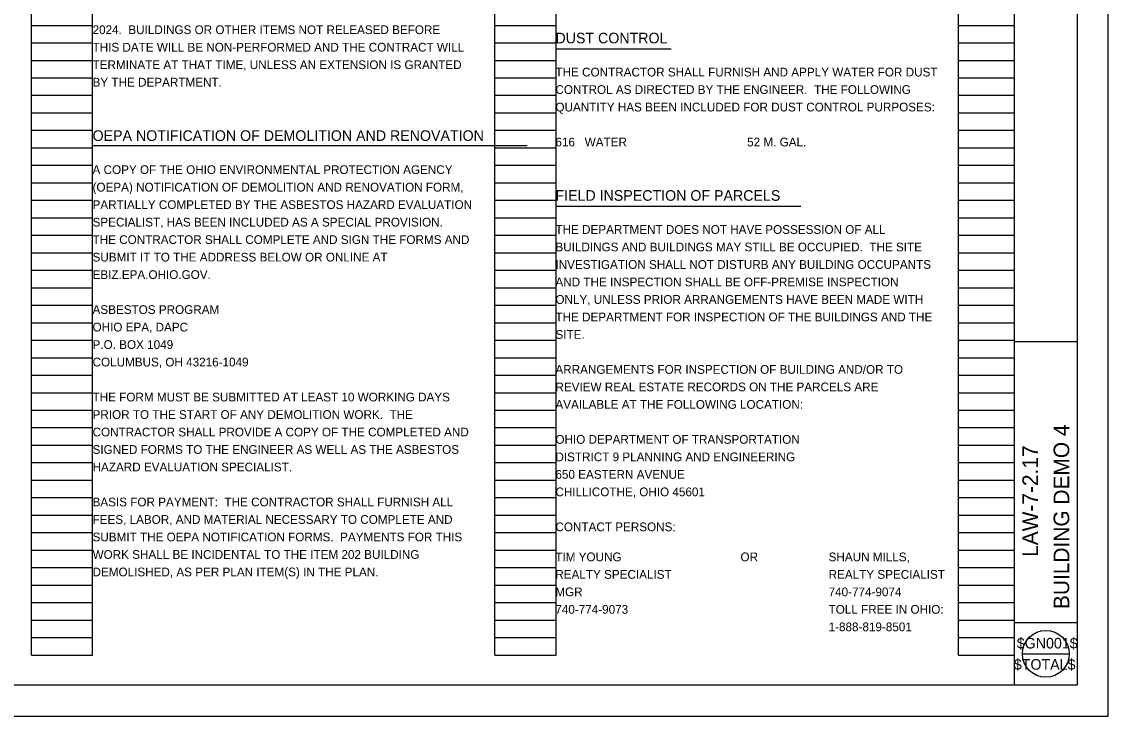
# Model space of a CAD drawing. Extents: x 0 to 34, y 0 to 22.
# Drawn here: x 16.61 to 34, y 0 to 11.12 of the extents above; entities that cross this region are included whole.
import ezdxf

# ---------------------------------------------------------------- set-up
doc = ezdxf.new("R2010")
doc.units = 0
for name, color, linetype in [('Default', 7, 'Continuous'), ('SC_Scratch2', 7, 'Continuous'), ('SH_Border', 7, 'Continuous'), ('SH_Cut_Line', 7, 'Continuous'), ('SH_Data', 7, 'Continuous'), ('TX_P_1', 7, 'Continuous')]:
    doc.layers.add(name, color=color, linetype=linetype)

msp = doc.modelspace()

# ---------------------------------------------------------------- linework, layer by layer
at = {"layer": 'SC_Scratch2'}
for p, q in [((16.76, 0.98), (16.76, 21.14)), ((17.74, 0.98), (17.74, 21.14)), ((24.18, 0.98), (24.18, 21.14)), ((25.16, 0.98), (25.16, 21.14)), ((31.6, 0.98), (31.6, 21.14)), ((32.5, 0.98), (32.5, 21.14)), ((16.76, 11.06), (17.74, 11.06)), ((24.18, 11.06), (25.16, 11.06)), ((31.6, 11.06), (32.5, 11.06)), ((16.76, 10.78), (17.74, 10.78)), ((24.18, 10.78), (25.16, 10.78)), ((31.6, 10.78), (32.5, 10.78)), ((16.76, 10.5), (17.74, 10.5)), ((24.18, 10.5), (25.16, 10.5)), ((31.6, 10.5), (32.5, 10.5)), ((16.76, 10.22), (17.74, 10.22)), ((24.18, 10.22), (25.16, 10.22)), ((31.6, 10.22), (32.5, 10.22)), ((16.76, 9.94), (17.74, 9.94)), ((24.18, 9.94), (25.16, 9.94)), ((31.6, 9.94), (32.5, 9.94)), ((16.76, 9.66), (17.74, 9.66)), ((24.18, 9.66), (25.16, 9.66)), ((31.6, 9.66), (32.5, 9.66)), ((16.76, 9.38), (17.74, 9.38)), ((24.18, 9.38), (25.16, 9.38)), ((31.6, 9.38), (32.5, 9.38)), ((16.76, 9.1), (17.74, 9.1)), ((24.18, 9.1), (25.16, 9.1)), ((31.6, 9.1), (32.5, 9.1)), ((16.76, 8.82), (17.74, 8.82)), ((24.18, 8.82), (25.16, 8.82)), ((31.6, 8.82), (32.5, 8.82)), ((16.76, 8.54), (17.74, 8.54)), ((24.18, 8.54), (25.16, 8.54)), ((31.6, 8.54), (32.5, 8.54)), ((16.76, 8.26), (17.74, 8.26)), ((24.18, 8.26), (25.16, 8.26)), ((31.6, 8.26), (32.5, 8.26)), ((16.76, 7.98), (17.74, 7.98)), ((24.18, 7.98), (25.16, 7.98)), ((31.6, 7.98), (32.5, 7.98)), ((16.76, 7.7), (17.74, 7.7)), ((24.18, 7.7), (25.16, 7.7)), ((31.6, 7.7), (32.5, 7.7)), ((16.76, 7.42), (17.74, 7.42)), ((24.18, 7.42), (25.16, 7.42)), ((31.6, 7.42), (32.5, 7.42)), ((16.76, 7.14), (17.74, 7.14)), ((24.18, 7.14), (25.16, 7.14)), ((31.6, 7.14), (32.5, 7.14)), ((16.76, 6.86), (17.74, 6.86)), ((24.18, 6.86), (25.16, 6.86)), ((31.6, 6.86), (32.5, 6.86)), ((16.76, 6.58), (17.74, 6.58)), ((24.18, 6.58), (25.16, 6.58)), ((31.6, 6.58), (32.5, 6.58)), ((16.76, 6.3), (17.74, 6.3)), ((24.18, 6.3), (25.16, 6.3)), ((31.6, 6.3), (32.5, 6.3)), ((16.76, 6.02), (17.74, 6.02)), ((24.18, 6.02), (25.16, 6.02)), ((31.6, 6.02), (32.5, 6.02)), ((16.76, 5.74), (17.74, 5.74)), ((24.18, 5.74), (25.16, 5.74)), ((31.6, 5.74), (32.5, 5.74)), ((16.76, 5.46), (17.74, 5.46)), ((24.18, 5.46), (25.16, 5.46)), ((31.6, 5.46), (32.5, 5.46)), ((16.76, 5.18), (17.74, 5.18)), ((24.18, 5.18), (25.16, 5.18)), ((31.6, 5.18), (32.5, 5.18)), ((16.76, 4.9), (17.74, 4.9)), ((24.18, 4.9), (25.16, 4.9)), ((31.6, 4.9), (32.5, 4.9)), ((16.76, 4.62), (17.74, 4.62)), ((24.18, 4.62), (25.16, 4.62)), ((31.6, 4.62), (32.5, 4.62)), ((16.76, 4.34), (17.74, 4.34)), ((24.18, 4.34), (25.16, 4.34)), ((31.6, 4.34), (32.5, 4.34)), ((16.76, 4.06), (17.74, 4.06)), ((24.18, 4.06), (25.16, 4.06)), ((31.6, 4.06), (32.5, 4.06)), ((16.76, 3.78), (17.74, 3.78)), ((24.18, 3.78), (25.16, 3.78)), ((31.6, 3.78), (32.5, 3.78)), ((16.76, 3.5), (17.74, 3.5)), ((24.18, 3.5), (25.16, 3.5)), ((31.6, 3.5), (32.5, 3.5)), ((16.76, 3.22), (17.74, 3.22)), ((24.18, 3.22), (25.16, 3.22)), ((31.6, 3.22), (32.5, 3.22)), ((16.76, 2.94), (17.74, 2.94)), ((24.18, 2.94), (25.16, 2.94)), ((31.6, 2.94), (32.5, 2.94)), ((16.76, 2.66), (17.74, 2.66)), ((24.18, 2.66), (25.16, 2.66)), ((31.6, 2.66), (32.5, 2.66)), ((16.76, 2.38), (17.74, 2.38)), ((24.18, 2.38), (25.16, 2.38)), ((31.6, 2.38), (32.5, 2.38)), ((16.76, 2.1), (17.74, 2.1)), ((24.18, 2.1), (25.16, 2.1)), ((31.6, 2.1), (32.5, 2.1)), ((16.76, 1.82), (17.74, 1.82)), ((24.18, 1.82), (25.16, 1.82)), ((31.6, 1.82), (32.5, 1.82)), ((16.76, 1.54), (17.74, 1.54)), ((24.18, 1.54), (25.16, 1.54)), ((31.6, 1.54), (32.5, 1.54)), ((16.76, 1.26), (17.74, 1.26)), ((24.18, 1.26), (25.16, 1.26)), ((31.6, 1.26), (32.5, 1.26)), ((16.76, 0.98), (17.74, 0.98)), ((24.18, 0.98), (25.16, 0.98)), ((31.6, 0.98), (32.5, 0.98))]:
    msp.add_line(p, q, dxfattribs=at)
at = {"layer": 'SH_Border'}
for p, q in [((32.5, 0.5), (32.5, 21.5)), ((32.5, 6), (33.5, 6)), ((32.5, 1.5), (33.5, 1.5))]:
    msp.add_line(p, q, dxfattribs=at)
msp.add_lwpolyline([(2, 21.5), (33.5, 21.5), (33.5, 0.5), (2, 0.5)], close=True, dxfattribs=at)
at = {"layer": 'SH_Cut_Line'}
msp.add_lwpolyline([(0, 0), (34, 0), (34, 22), (0, 22)], close=True, dxfattribs=at)
at = {"layer": 'SH_Data'}
for p, q in [((33, 3.792), (33, 3.792)), ((33, 1.085), (33, 1.085)), ((32.625, 1), (33.375, 1)), ((33, 0.745), (33, 0.745))]:
    msp.add_line(p, q, dxfattribs=at)
msp.add_circle((33, 1), 0.375, dxfattribs=at)
at = {"layer": 'TX_P_1'}
for p, q in [((25.157, 10.685), (27, 10.685)), ((17.747, 9.138), (24.698, 9.138)), ((25.157, 8.165), (29.079, 8.165))]:
    msp.add_line(p, q, dxfattribs=at)

# ---------------------------------------------------------------- texts
at = {"layer": 'Default'}
for s, p in [('TIM YOUNG', (25.148, 2.481)), ('OR', (28.112, 2.481)), ('SHAUN MILLS,', (29.523, 2.481)), ('REALTY SPECIALIST', (25.148, 2.201)), ('REALTY SPECIALIST', (29.523, 2.201)), ('MGR', (25.148, 1.921)), ('740-774-9074', (29.523, 1.921)), ('740-774-9073', (25.148, 1.641)), ('TOLL FREE IN OHIO:', (29.523, 1.641)), ('1-888-819-8501', (29.523, 1.361))]:
    msp.add_text(s, height=0.14, dxfattribs=at).set_placement(p)
at = {"layer": 'SH_Data'}
for s, p in [('BUILDING DEMO 4', (33.375, 1.717)), ('LAW-7-2.17', (32.875, 2.552))]:
    msp.add_text(s, height=0.25, rotation=90, dxfattribs=at).set_placement(p)
for s, p in [('$GN001$', (32.536, 1.085)), ('$TOTAL$', (32.489, 0.745))]:
    msp.add_text(s, height=0.17, dxfattribs=at).set_placement(p)
at = {"layer": 'TX_P_1'}
for s, height, p in [('2024.  BUILDINGS OR OTHER ITEMS NOT RELEASED BEFORE ', 0.14, (17.74, 10.92)), ('DUST CONTROL', 0.17, (25.15, 10.772)), ('THIS DATE WILL BE NON-PERFORMED AND THE CONTRACT WILL ', 0.14, (17.74, 10.64)), ('TERMINATE AT THAT TIME, UNLESS AN EXTENSION IS GRANTED ', 0.14, (17.74, 10.36)), ('THE CONTRACTOR SHALL FURNISH AND APPLY WATER FOR DUST ', 0.14, (25.15, 10.242)), ('BY THE DEPARTMENT.', 0.14, (17.74, 10.08)), ('CONTROL AS DIRECTED BY THE ENGINEER.  THE FOLLOWING ', 0.14, (25.15, 9.962)), ('QUANTITY HAS BEEN INCLUDED FOR DUST CONTROL PURPOSES:', 0.14, (25.15, 9.682)), ('OEPA NOTIFICATION OF DEMOLITION AND RENOVATION', 0.17, (17.74, 9.21)), ('616   WATER                                     52 M. GAL.', 0.14, (25.15, 9.122)), ('A COPY OF THE OHIO ENVIRONMENTAL PROTECTION AGENCY', 0.14, (17.74, 8.68)), ('(OEPA) NOTIFICATION OF DEMOLITION AND RENOVATION FORM, ', 0.14, (17.74, 8.4)), ('FIELD INSPECTION OF PARCELS', 0.17, (25.15, 8.252)), ('PARTIALLY COMPLETED BY THE ASBESTOS HAZARD EVALUATION ', 0.14, (17.74, 8.12)), ('SPECIALIST, HAS BEEN INCLUDED AS A SPECIAL PROVISION.  ', 0.14, (17.74, 7.84)), ('THE DEPARTMENT DOES NOT HAVE POSSESSION OF ALL ', 0.14, (25.15, 7.722)), ('THE CONTRACTOR SHALL COMPLETE AND SIGN THE FORMS AND ', 0.14, (17.74, 7.56)), ('BUILDINGS AND BUILDINGS MAY STILL BE OCCUPIED.  THE SITE ', 0.14, (25.15, 7.442)), ('SUBMIT IT TO THE ADDRESS BELOW OR ONLINE AT ', 0.14, (17.74, 7.28)), ('EBIZ.EPA.OHIO.GOV. ', 0.14, (17.74, 7)), ('INVESTIGATION SHALL NOT DISTURB ANY BUILDING OCCUPANTS ', 0.14, (25.15, 7.162)), ('AND THE INSPECTION SHALL BE OFF-PREMISE INSPECTION ', 0.14, (25.15, 6.882)), ('ONLY, UNLESS PRIOR ARRANGEMENTS HAVE BEEN MADE WITH ', 0.14, (25.15, 6.602)), ('ASBESTOS PROGRAM', 0.14, (17.74, 6.44)), ('THE DEPARTMENT FOR INSPECTION OF THE BUILDINGS AND THE ', 0.14, (25.15, 6.322)), ('OHIO EPA, DAPC', 0.14, (17.74, 6.16)), ('SITE.', 0.14, (25.15, 6.042)), ('P.O. BOX 1049', 0.14, (17.74, 5.88)), ('COLUMBUS, OH 43216-1049', 0.14, (17.74, 5.6)), ('ARRANGEMENTS FOR INSPECTION OF BUILDING AND/OR TO ', 0.14, (25.15, 5.482)), ('REVIEW REAL ESTATE RECORDS ON THE PARCELS ARE ', 0.14, (25.15, 5.202)), ('THE FORM MUST BE SUBMITTED AT LEAST 10 WORKING DAYS ', 0.14, (17.74, 5.04)), ('AVAILABLE AT THE FOLLOWING LOCATION:', 0.14, (25.15, 4.922)), ('PRIOR TO THE START OF ANY DEMOLITION WORK.  THE ', 0.14, (17.74, 4.76)), ('CONTRACTOR SHALL PROVIDE A COPY OF THE COMPLETED AND ', 0.14, (17.74, 4.48)), ('OHIO DEPARTMENT OF TRANSPORTATION', 0.14, (25.15, 4.362)), ('SIGNED FORMS TO THE ENGINEER AS WELL AS THE ASBESTOS ', 0.14, (17.74, 4.2)), ('DISTRICT 9 PLANNING AND ENGINEERING', 0.14, (25.15, 4.082)), ('HAZARD EVALUATION SPECIALIST.', 0.14, (17.74, 3.92)), ('650 EASTERN AVENUE', 0.14, (25.15, 3.802)), ('CHILLICOTHE, OHIO 45601', 0.14, (25.15, 3.522)), ('BASIS FOR PAYMENT:  THE CONTRACTOR SHALL FURNISH ALL ', 0.14, (17.74, 3.36)), ('FEES, LABOR, AND MATERIAL NECESSARY TO COMPLETE AND ', 0.14, (17.74, 3.08)), ('CONTACT PERSONS:', 0.14, (25.15, 2.962)), ('SUBMIT THE OEPA NOTIFICATION FORMS.  PAYMENTS FOR THIS ', 0.14, (17.74, 2.8)), ('WORK SHALL BE INCIDENTAL TO THE ITEM 202 BUILDING ', 0.14, (17.74, 2.52)), ('DEMOLISHED, AS PER PLAN ITEM(S) IN THE PLAN.', 0.14, (17.74, 2.24))]:
    msp.add_text(s, height=height, dxfattribs=at).set_placement(p)

doc.saveas('drawing.dxf')
